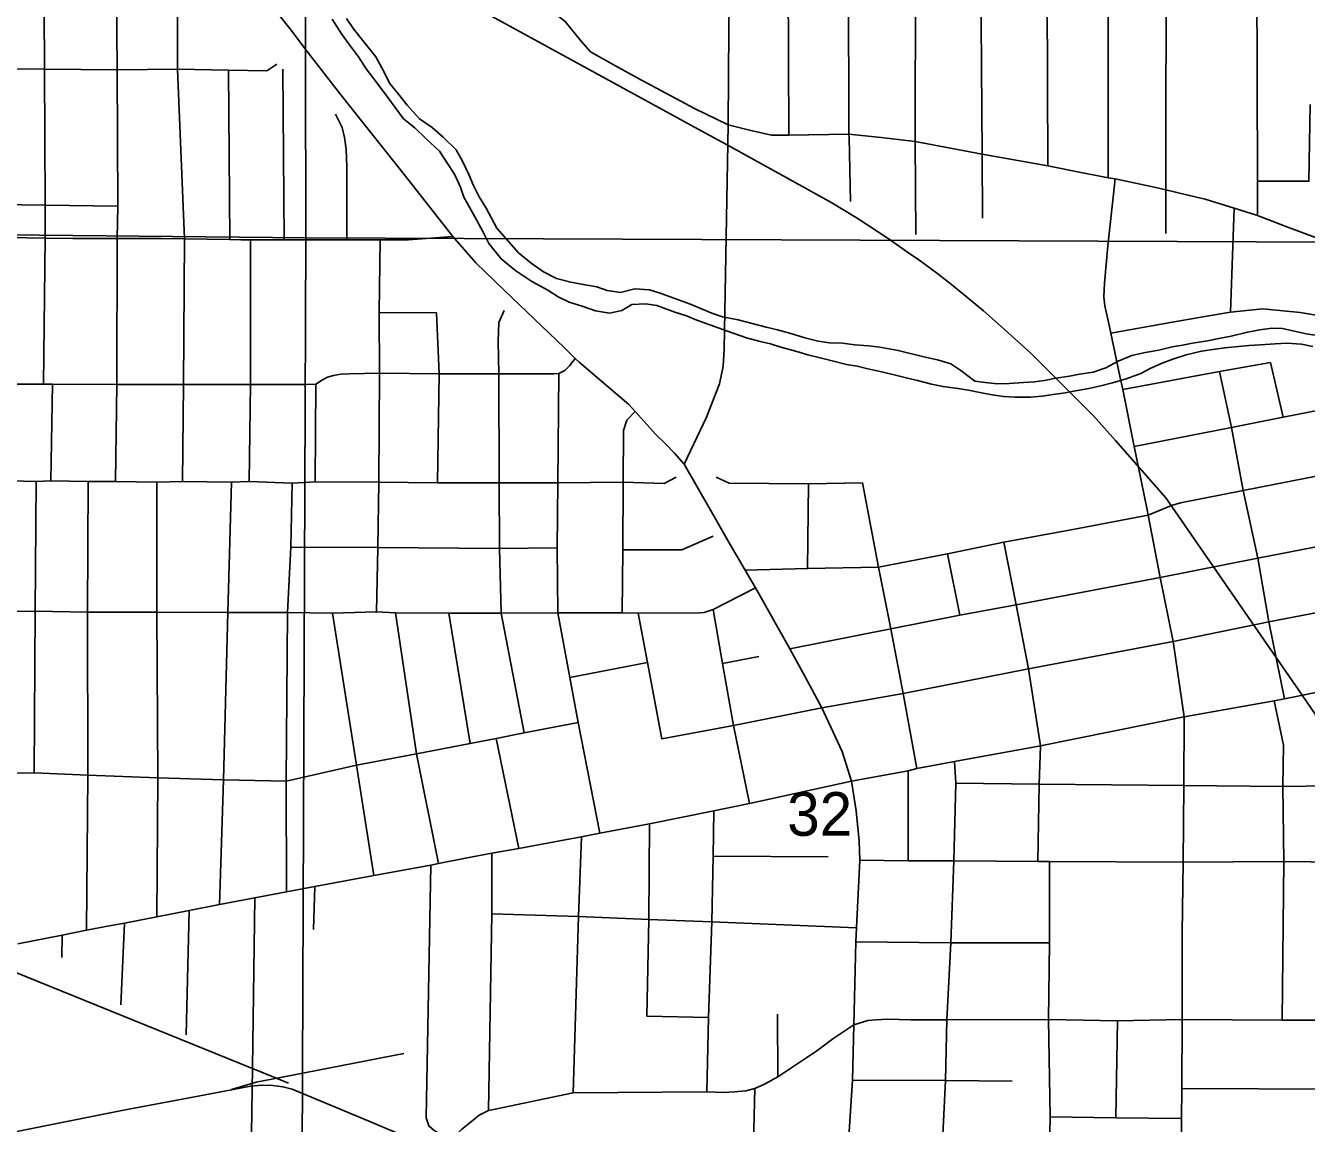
# Model space of a CAD drawing. Extents: x 0 to 34, y 0 to 22.
# Drawn here: x 3.784 to 5.012, y 17.64 to 18.692 of the extents above; entities that cross this region are included whole.
import ezdxf

# ---------------------------------------------------------------- set-up
doc = ezdxf.new("R2010")
doc.units = 0
for name, color, linetype in [('GM_X_City_Street', 7, 'Continuous'), ('GM_X_County_Road', 7, 'Continuous'), ('GM_X_Minor_River', 7, 'Continuous'), ('GM_X_Rail_Line', 7, 'Continuous'), ('GM_X_Section', 7, 'Continuous'), ('GM_X_Section_Text', 7, 'Continuous')]:
    doc.layers.add(name, color=color, linetype=linetype)

msp = doc.modelspace()

# ---------------------------------------------------------------- linework, layer by layer
at = {"layer": 'GM_X_City_Street'}
for p, q in [((4.7639, 18.5577), (4.7631, 18.738)), ((4.8218, 18.5464), (4.8217, 18.7386)), ((3.98, 18.4872), (3.9787, 18.6496)), ((4.032, 18.487), (4.0306, 18.6504)), ((4.5749, 18.5237), (4.5734, 18.5851)), ((4.9389, 18.4177), (4.9425, 18.5171)), ((4.123, 18.4171), (4.1778, 18.4168)), ((4.9895, 18.3168), (4.9774, 18.3694)), ((3.8082, 18.2558), (3.8099, 18.3485)), ((4.0618, 18.2551), (4.0624, 18.3484)), ((4.5336, 18.1718), (4.5344, 18.2531)), ((4.6795, 18.127), (4.6677, 18.1859)), ((4.2102, 18.0043), (4.1898, 18.129)), ((4.4868, 18.0874), (4.4521, 18.0808)), ((4.3803, 18.0817), (4.3058, 18.0675)), ((4.2568, 17.9035), (4.235, 18.0088)), ((4.63, 17.8916), (4.63, 17.978)), ((4.4431, 17.8962), (4.5534, 17.8954)), ((4.0601, 17.8258), (4.0613, 17.8672)), ((3.9381, 17.725), (3.9408, 17.8441)), ((3.8755, 17.7537), (3.8788, 17.8321)), ((3.8188, 17.7991), (3.8191, 17.8204)), ((4.3796, 17.7427), (4.4387, 17.7414)), ((4.5052, 17.6847), (4.5048, 17.7447)), ((4.8292, 17.6455), (4.8306, 17.7384)), ((4.8925, 17.6736), (5.0807, 17.6725))]:
    msp.add_line(p, q, dxfattribs=at)
for points in [[(4.5157, 18.5873), (4.5151, 18.7357), (4.5148, 18.8383)], [(3.8013, 18.3485), (3.8028, 18.4885), (3.8027, 18.5202), (3.8022, 18.6503), (3.8015, 18.7653), (3.8005, 18.8017), (3.8009, 18.8075), (3.8032, 18.8129), (3.8059, 18.8174), (3.8104, 18.8201), (3.8174, 18.8217), (3.8338, 18.8167)], [(3.8704, 18.2554), (3.8715, 18.3481), (3.8719, 18.4882), (3.8724, 18.5193), (3.8719, 18.6498), (3.8709, 18.7646), (3.8712, 18.8003), (3.8696, 18.8038), (3.8661, 18.8059), (3.8518, 18.8109), (3.8338, 18.8167)], [(3.9344, 18.2554), (3.9354, 18.3481), (3.9363, 18.4878), (3.9297, 18.6503), (3.9294, 18.7641), (3.9291, 18.7948)], [(4.5734, 18.5851), (4.5733, 18.5881), (4.5728, 18.7371)], [(4.6375, 18.4919), (4.6368, 18.581), (4.6371, 18.7379)], [(4.7013, 18.5077), (4.7011, 18.5691), (4.6996, 18.738)], [(4.8769, 18.4929), (4.8772, 18.5348), (4.8772, 18.5726), (4.8774, 18.7392)], [(4.964, 18.5105), (4.9649, 18.5114), (4.9648, 18.543), (4.9644, 18.7399)], [(4.2923, 18.7032), (4.3013, 18.6962), (4.3163, 18.6777), (4.3255, 18.6672), (4.3496, 18.6537), (4.371, 18.6419), (4.4251, 18.6126), (4.4575, 18.5971), (4.4793, 18.5918), (4.4991, 18.5873), (4.5157, 18.5873), (4.5733, 18.5881), (4.6043, 18.585), (4.6368, 18.581), (4.7011, 18.5691), (4.7639, 18.5577), (4.7972, 18.551), (4.809, 18.5488)], [(3.5997, 18.6513), (3.6641, 18.6509), (3.7331, 18.6511), (3.8022, 18.6503), (3.8719, 18.6498), (3.9297, 18.6503), (3.9787, 18.6496), (4.0152, 18.649), (4.0249, 18.6552)], [(4.9648, 18.543), (5.0142, 18.543), (5.0155, 18.6165)], [(4.092, 18.487), (4.092, 18.5568), (4.0915, 18.5738), (4.0897, 18.585), (4.0875, 18.5944), (4.0812, 18.6074)], [(4.809, 18.5488), (4.8218, 18.5464), (4.8284, 18.5452), (4.8674, 18.5369)], [(4.8227, 18.4051), (4.8185, 18.4235), (4.8175, 18.4324), (4.8181, 18.4453), (4.8216, 18.4812), (4.8284, 18.5452)], [(4.8674, 18.5369), (4.8772, 18.5348), (4.8969, 18.53)], [(4.8969, 18.53), (4.9146, 18.5257), (4.9425, 18.5171), (4.964, 18.5105), (4.965, 18.5102)], [(3.665, 18.5214), (3.734, 18.5211), (3.8027, 18.5202), (3.8724, 18.5193)], [(4.965, 18.5102), (4.9931, 18.4995), (5.023, 18.4882), (5.0685, 18.4711)], [(3.9984, 18.2554), (3.9998, 18.3481), (3.9996, 18.487)], [(4.1203, 18.1302), (4.1216, 18.1921), (4.1228, 18.2546), (4.1233, 18.359), (4.123, 18.4171), (4.1241, 18.487)], [(4.1789, 18.2541), (4.1804, 18.3586), (4.1778, 18.4168)], [(4.2621, 18.0145), (4.2399, 18.129), (4.2384, 18.1912), (4.2379, 18.2541), (4.2376, 18.3586), (4.2372, 18.3895), (4.2376, 18.4078), (4.2427, 18.4193)], [(4.8244, 18.3974), (4.8814, 18.4077), (4.9145, 18.4134), (4.9389, 18.4177), (4.97, 18.4209), (4.9764, 18.4202), (5.0058, 18.4172), (5.0685, 18.4066), (5.1056, 18.4003), (5.1258, 18.3975), (5.1402, 18.3945), (5.1892, 18.3828), (5.2629, 18.3574), (5.3225, 18.3403), (5.3816, 18.321), (5.4194, 18.3087), (5.4397, 18.3021), (5.455, 18.2985), (5.5002, 18.2901)], [(4.833, 18.3562), (4.8244, 18.3974), (4.8227, 18.4051)], [(3.6633, 18.3494), (3.6653, 18.3494), (3.7322, 18.3485), (3.8013, 18.3485), (3.8099, 18.3485), (3.8715, 18.3481), (3.9354, 18.3481), (3.9998, 18.3481), (4.0526, 18.3482), (4.0624, 18.3484), (4.0686, 18.3526), (4.0735, 18.3553), (4.0792, 18.3568), (4.0861, 18.358), (4.0942, 18.3585), (4.1233, 18.359), (4.1804, 18.3586), (4.2376, 18.3586), (4.2855, 18.3583), (4.2903, 18.3583), (4.2953, 18.3589), (4.3009, 18.3615), (4.3054, 18.366), (4.311, 18.3732)], [(4.8357, 18.3435), (4.9286, 18.3606), (4.9774, 18.3694)], [(4.3345, 17.9182), (4.3139, 18.0242), (4.3058, 18.0675), (4.2942, 18.1294), (4.2937, 18.1917), (4.2943, 18.254), (4.2953, 18.3589)], [(4.8591, 18.228), (4.8506, 18.2704), (4.8466, 18.2889), (4.8357, 18.3435), (4.833, 18.3562)], [(4.9908, 18.0471), (4.9759, 18.1208), (4.9653, 18.1819), (4.9513, 18.2465), (4.9401, 18.3071), (4.9286, 18.3606)], [(4.8466, 18.2889), (4.9401, 18.3071), (4.9895, 18.3168), (5.0666, 18.3319), (5.1349, 18.3451), (5.1807, 18.33), (5.2547, 18.3072), (5.3459, 18.2743)], [(4.3558, 18.1293), (4.3567, 18.1899), (4.357, 18.2545), (4.3571, 18.3043), (4.3603, 18.3142), (4.3683, 18.3224)], [(4.4738, 18.1703), (4.5336, 18.1718), (4.6016, 18.173), (4.6677, 18.1859), (4.7217, 18.1972), (4.7878, 18.2093), (4.8601, 18.223), (4.8824, 18.2321), (4.891, 18.2348), (4.9513, 18.2465), (5.0767, 18.2711)], [(3.7333, 18.2568), (3.7941, 18.2554), (3.8082, 18.2558), (3.8441, 18.2554), (3.8704, 18.2554), (3.9099, 18.2545), (3.9344, 18.2554), (3.9816, 18.2545), (3.9984, 18.2554), (4.0397, 18.2536), (4.0618, 18.2551), (4.1228, 18.2546), (4.1789, 18.2541), (4.2379, 18.2541), (4.2943, 18.254), (4.357, 18.2545), (4.3961, 18.2535), (4.4076, 18.2595)], [(4.4459, 18.2595), (4.4586, 18.2536), (4.5344, 18.2531), (4.5862, 18.2539)], [(5.427, 18.2509), (5.3978, 18.2584), (5.3849, 18.2618), (5.3799, 18.262), (5.3739, 18.2608), (5.3617, 18.2586), (5.3452, 18.2552), (5.2442, 18.2367), (5.1724, 18.2226), (5.0904, 18.2061), (4.9653, 18.1819), (4.8716, 18.1633), (4.7336, 18.1371), (4.6795, 18.127), (4.6136, 18.1142), (4.5165, 18.0948)], [(3.7923, 17.976), (3.7933, 18.1311), (3.7941, 18.2554)], [(3.8426, 17.8251), (3.8439, 17.9739), (3.8435, 18.13), (3.8441, 18.2554)], [(3.9098, 17.8381), (3.9108, 17.9713), (3.9099, 18.13), (3.9099, 18.2545)], [(3.9698, 17.8498), (3.9739, 17.9692), (3.9778, 18.1296), (3.9816, 18.2545)], [(4.0341, 17.862), (4.0339, 17.9679), (4.035, 18.1298), (4.0382, 18.1922), (4.0397, 18.2536)], [(4.6383, 17.9801), (4.6253, 18.0522), (4.6136, 18.1142), (4.6016, 18.173), (4.5862, 18.2539)], [(4.8946, 18.0297), (4.884, 18.1018), (4.8716, 18.1633), (4.8601, 18.223), (4.8591, 18.228)], [(4.3938, 18.0085), (4.4627, 18.0213), (4.5474, 18.0382), (4.6253, 18.0522), (4.7455, 18.0758), (4.884, 18.1018), (4.9759, 18.1208), (5.1022, 18.145), (5.2069, 18.1661), (5.2356, 18.1707), (5.3407, 18.1919), (5.3573, 18.1952), (5.4357, 18.2104)], [(4.3567, 18.1899), (4.4132, 18.1899), (4.443, 18.203)], [(4.7568, 18.002), (4.7455, 18.0758), (4.7336, 18.1371), (4.7217, 18.1972)], [(4.0382, 18.1922), (4.1216, 18.1921), (4.2384, 18.1912), (4.2937, 18.1917)], [(4.8946, 18.0297), (4.9808, 18.045), (4.9908, 18.0471), (5.1161, 18.0723), (5.1925, 18.0873), (5.2219, 18.0934), (5.2784, 18.1052), (5.3074, 18.1106), (5.3545, 18.1194), (5.3643, 18.1212), (5.3826, 18.1248), (5.426, 18.1334), (5.4498, 18.1382), (5.4902, 18.1462), (5.528, 18.1531), (5.5468, 18.1593), (5.566, 18.1633)], [(3.7308, 18.1306), (3.7933, 18.1311), (3.8435, 18.13), (3.9099, 18.13), (3.9778, 18.1296), (4.035, 18.1298), (4.0784, 18.129), (4.1203, 18.1302), (4.1386, 18.1294), (4.1898, 18.129), (4.2399, 18.129), (4.2942, 18.1294), (4.3558, 18.1293), (4.3714, 18.129), (4.4301, 18.1293), (4.4344, 18.1298), (4.443, 18.1327), (4.4836, 18.1535)], [(4.4781, 17.9466), (4.4627, 18.0213), (4.4521, 18.0808), (4.443, 18.1327)], [(4.118, 17.8777), (4.1012, 17.9833), (4.0784, 18.129)], [(4.18, 17.889), (4.1587, 17.9942), (4.1386, 18.1294)], [(4.3938, 18.0085), (4.3803, 18.0817), (4.3714, 18.129)], [(4.9886, 17.7389), (4.99, 17.8911), (4.9893, 17.9628), (4.9898, 18.0026), (4.9808, 18.045)], [(3.296, 17.9794), (3.3466, 17.9778), (3.4172, 17.9776), (3.5342, 17.9772), (3.5976, 17.9768), (3.6612, 17.9767), (3.7277, 17.9767), (3.7808, 17.9756), (3.7923, 17.976), (3.8439, 17.9739), (3.9108, 17.9713), (3.9739, 17.9692), (4.0339, 17.9679), (4.1012, 17.9833), (4.1587, 17.9942), (4.2102, 18.0043), (4.235, 18.0088), (4.2621, 18.0145), (4.3139, 18.0242)], [(4.5759, 17.9679), (4.63, 17.978), (4.6383, 17.9801), (4.6746, 17.9868), (4.7568, 18.002), (4.8946, 18.0297)], [(4.8946, 17.4586), (4.8927, 17.5074), (4.8926, 17.5199), (4.8925, 17.5655), (4.8921, 17.6044), (4.8921, 17.6448), (4.8925, 17.6736), (4.8928, 17.7397), (4.8928, 17.8223), (4.8938, 17.8905), (4.8943, 17.9638), (4.8946, 18.0297)], [(4.7545, 17.8912), (4.7555, 17.9653), (4.7568, 18.002)], [(4.6738, 17.8916), (4.6756, 17.9661), (4.6746, 17.9868)], [(3.7765, 17.812), (3.8191, 17.8204), (3.8426, 17.8251), (3.8626, 17.829), (3.8788, 17.8321), (3.9098, 17.8381), (3.9408, 17.8441), (3.9698, 17.8498), (4.0039, 17.8562), (4.0341, 17.862), (4.0613, 17.8672), (4.0752, 17.8698), (4.118, 17.8777), (4.1726, 17.8876), (4.18, 17.889), (4.2057, 17.8943), (4.231, 17.8991), (4.2568, 17.9035), (4.3064, 17.9129), (4.3168, 17.9148), (4.3345, 17.9182), (4.382, 17.9273), (4.4439, 17.9397), (4.4781, 17.9466), (4.5759, 17.9679)], [(4.6756, 17.9661), (4.7555, 17.9653), (4.8943, 17.9638), (4.9893, 17.9628), (5.0335, 17.9635), (5.0519, 17.9614), (5.0781, 17.9578), (5.12, 17.9512), (5.2013, 17.9387)], [(4.4372, 17.6704), (4.4387, 17.7414), (4.442, 17.8333), (4.4431, 17.8962), (4.4439, 17.9397)], [(4.3796, 17.7427), (4.3814, 17.8355), (4.382, 17.9273)], [(4.3091, 17.6692), (4.3141, 17.8383), (4.3168, 17.9148)], [(4.5836, 17.8922), (4.63, 17.8916), (4.6738, 17.8916), (4.7545, 17.8912), (4.7656, 17.8911), (4.8938, 17.8905), (4.99, 17.8911), (5.0672, 17.8902), (5.1126, 17.8907), (5.1933, 17.888), (5.2606, 17.8879), (5.2922, 17.8883), (5.3133, 17.8892), (5.3279, 17.8895), (5.3741, 17.8904), (5.3818, 17.8914), (5.456, 17.9009), (5.5128, 17.9074)], [(4.1942, 17.6262), (4.1801, 17.6307), (4.1758, 17.6333), (4.1707, 17.6376), (4.1681, 17.6453), (4.1726, 17.8876)], [(4.2278, 17.6524), (4.2309, 17.841), (4.231, 17.8991)], [(4.6669, 17.586), (4.6633, 17.5928), (4.6624, 17.5969), (4.6632, 17.6292), (4.666, 17.6811), (4.6672, 17.7392), (4.6711, 17.8132), (4.6738, 17.8916)], [(4.7641, 17.5672), (4.7662, 17.644), (4.7662, 17.6463), (4.7647, 17.7396), (4.7654, 17.8132), (4.7656, 17.8911)], [(3.9999, 17.5871), (4.0015, 17.6935), (4.0039, 17.8562)], [(4.2309, 17.841), (4.3141, 17.8383), (4.3814, 17.8355), (4.442, 17.8333), (4.5806, 17.8276)], [(4.58, 17.814), (4.6711, 17.8132), (4.7654, 17.8132)], [(4.2343, 17.6538), (4.3091, 17.6692), (4.4372, 17.6704), (4.4526, 17.6698), (4.4637, 17.6703), (4.4745, 17.6714), (4.4831, 17.6736), (4.4925, 17.6778), (4.5052, 17.6847), (4.5425, 17.7096), (4.5577, 17.7211), (4.5779, 17.7346)], [(4.5779, 17.7346), (4.5913, 17.7388), (4.5994, 17.7394), (4.6102, 17.7398), (4.6326, 17.7394), (4.6672, 17.7392), (4.7647, 17.7396), (4.8306, 17.7384), (4.8928, 17.7397), (4.9886, 17.7389), (5.0457, 17.7389), (5.0902, 17.739), (5.1727, 17.7377)], [(4.5766, 17.6815), (4.666, 17.6811), (4.7296, 17.6806)], [(4.4878, 17.6169), (4.4819, 17.621), (4.4831, 17.6736)], [(3.7696, 17.5067), (3.8107, 17.5145), (3.9018, 17.5292), (3.9512, 17.5379), (4.006, 17.5472), (4.0098, 17.5479), (4.0719, 17.557), (4.1372, 17.5684), (4.1439, 17.5703), (4.1504, 17.5728), (4.1551, 17.575), (4.1633, 17.581), (4.1694, 17.5862), (4.1762, 17.5931), (4.1837, 17.6055), (4.1879, 17.6125), (4.1911, 17.6194), (4.1942, 17.6262), (4.2019, 17.6342), (4.2098, 17.6407), (4.2187, 17.6479), (4.2278, 17.6524), (4.2343, 17.6538)], [(4.7662, 17.6463), (4.8292, 17.6455), (4.8921, 17.6448)]]:
    msp.add_lwpolyline(points, dxfattribs=at)
at = {"layer": 'GM_X_County_Road'}
for points in [[(4.4575, 18.5971), (4.4585, 18.7358), (4.4579, 18.8372), (4.4596, 18.9102), (4.4579, 18.9712), (4.4578, 18.9772)], [(3.7317, 18.8659), (3.8144, 18.8416), (3.8859, 18.8163), (3.9095, 18.8064), (3.9291, 18.7948), (3.9423, 18.7865), (3.9632, 18.7706), (3.9784, 18.7571), (3.995, 18.741), (4.0106, 18.7234), (4.0385, 18.6879), (4.0519, 18.6704), (4.0861, 18.6257), (4.1483, 18.5479), (4.1937, 18.4902), (4.2156, 18.4647), (4.243, 18.4383), (4.3002, 18.3836)], [(4.4155, 18.272), (4.4369, 18.3169), (4.4493, 18.349), (4.4527, 18.3657), (4.4536, 18.3821), (4.4575, 18.5971)], [(3.6642, 18.49), (3.7342, 18.4893), (3.75, 18.4893), (3.8028, 18.4885), (3.8293, 18.4882), (3.8719, 18.4882), (3.9145, 18.4882), (3.9363, 18.4878), (3.98, 18.4872), (3.9903, 18.487), (3.9996, 18.487), (4.032, 18.487), (4.092, 18.487), (4.1241, 18.487), (4.1512, 18.487), (4.1937, 18.4902)], [(4.3002, 18.3836), (4.311, 18.3732), (4.3148, 18.3696), (4.3622, 18.3292), (4.3683, 18.3224), (4.3745, 18.3155), (4.3875, 18.301), (4.3971, 18.2918), (4.4061, 18.2824), (4.4155, 18.272), (4.4391, 18.2308), (4.4585, 18.1965), (4.4738, 18.1703), (4.4836, 18.1535), (4.4877, 18.1465), (4.5165, 18.0948), (4.5314, 18.068), (4.5474, 18.0382), (4.5669, 17.9964), (4.5759, 17.9679)], [(4.5759, 17.9679), (4.5801, 17.9395), (4.5831, 17.9107), (4.5836, 17.8922), (4.5806, 17.8276), (4.58, 17.814), (4.5786, 17.7603), (4.5779, 17.7346), (4.5766, 17.6815), (4.5729, 17.6225), (4.5718, 17.6034), (4.5706, 17.5721), (4.5704, 17.5667), (4.5702, 17.5616), (4.5689, 17.5355)]]:
    msp.add_lwpolyline(points, dxfattribs=at)
at = {"layer": 'GM_X_Minor_River'}
for points in [[(4.078, 18.6985), (4.0868, 18.6843), (4.0946, 18.6739), (4.1031, 18.6623), (4.1105, 18.6507), (4.1179, 18.6411), (4.1286, 18.6268), (4.1382, 18.6137), (4.1464, 18.6029), (4.1572, 18.5943), (4.1677, 18.5839), (4.1807, 18.5718), (4.1885, 18.5599), (4.1951, 18.5499), (4.2009, 18.5372), (4.2042, 18.5277), (4.21, 18.5177), (4.2163, 18.5061), (4.2225, 18.495), (4.228, 18.4835), (4.2398, 18.4688), (4.254, 18.4571), (4.2694, 18.4469), (4.2848, 18.4386), (4.2946, 18.4324), (4.3051, 18.4272), (4.3176, 18.4232), (4.3304, 18.4187), (4.3437, 18.4166), (4.3555, 18.419), (4.3651, 18.4249), (4.3784, 18.4257), (4.389, 18.424), (4.4064, 18.4176), (4.4177, 18.4139), (4.4275, 18.4099), (4.4524, 18.401), (4.4622, 18.3974), (4.475, 18.393), (4.4882, 18.3893), (4.4981, 18.3872), (4.5079, 18.384), (4.5234, 18.3799), (4.5339, 18.3766), (4.5457, 18.3737), (4.5559, 18.3712), (4.571, 18.3675), (4.5812, 18.3658), (4.5914, 18.3633), (4.6032, 18.3608), (4.6168, 18.3574), (4.6281, 18.3546), (4.6391, 18.3521), (4.6523, 18.3487), (4.6636, 18.3462), (4.6777, 18.3444), (4.6879, 18.3427), (4.6989, 18.3406), (4.7087, 18.3385), (4.7216, 18.3367), (4.7322, 18.3361), (4.7474, 18.3362), (4.7584, 18.3371), (4.7691, 18.3388), (4.7805, 18.3404), (4.7904, 18.3421), (4.8034, 18.3445), (4.8149, 18.347), (4.8259, 18.3498), (4.8389, 18.3537), (4.8531, 18.3587), (4.8627, 18.3638), (4.8734, 18.3686), (4.8837, 18.3725), (4.8964, 18.3768), (4.9112, 18.3803), (4.9242, 18.382), (4.9337, 18.3833), (4.9466, 18.3846), (4.9565, 18.3855), (4.9676, 18.3864), (4.982, 18.3873), (4.9931, 18.3878), (5.0071, 18.3868), (5.0181, 18.3846)], [(5.0266, 18.3947), (5.0115, 18.3969), (4.9888, 18.4019), (4.9785, 18.4022), (4.9671, 18.4005), (4.9553, 18.3984), (4.9396, 18.3946), (4.9278, 18.3922), (4.9171, 18.3901), (4.9026, 18.3877), (4.8931, 18.386), (4.8832, 18.3843), (4.8702, 18.3812), (4.8573, 18.3788), (4.8443, 18.376), (4.8313, 18.3706), (4.8194, 18.3643), (4.8075, 18.36), (4.7942, 18.358), (4.7846, 18.3563), (4.7717, 18.3543), (4.7606, 18.3522), (4.7511, 18.3509), (4.7405, 18.35), (4.7268, 18.3491), (4.7154, 18.349), (4.704, 18.35), (4.6941, 18.3513), (4.6807, 18.3615), (4.6709, 18.3681), (4.6581, 18.3718), (4.6452, 18.3747), (4.6206, 18.3809), (4.6029, 18.3839), (4.5919, 18.3853), (4.579, 18.3863), (4.5672, 18.3877), (4.5547, 18.3883), (4.5437, 18.3897), (4.5309, 18.393), (4.5176, 18.3971), (4.5048, 18.4007), (4.4938, 18.4032), (4.4806, 18.4066), (4.467, 18.4102), (4.4522, 18.4132), (4.442, 18.4165), (4.4319, 18.4208), (4.4206, 18.4256), (4.3923, 18.4357), (4.3821, 18.4389), (4.3681, 18.44), (4.3543, 18.4365), (4.3414, 18.4383), (4.3316, 18.4419), (4.3203, 18.4436), (4.3066, 18.4462), (4.293, 18.4499), (4.2806, 18.4562), (4.2686, 18.4644), (4.2567, 18.4745), (4.2474, 18.485), (4.2359, 18.4981), (4.2256, 18.5173), (4.219, 18.5281), (4.2131, 18.5396), (4.2088, 18.5496), (4.2029, 18.5623), (4.1967, 18.573), (4.1844, 18.5854), (4.1739, 18.5944), (4.1616, 18.603), (4.1497, 18.6158), (4.1415, 18.6266), (4.133, 18.637), (4.1275, 18.6481), (4.1198, 18.6623), (4.1083, 18.6766), (4.0983, 18.689), (4.0917, 18.699)]]:
    msp.add_lwpolyline(points, dxfattribs=at)
at = {"layer": 'GM_X_Rail_Line'}
msp.add_line((4.0235, 17.6837), (4.0361, 17.6786), dxfattribs=at)
for points in [[(4.4322, 18.5911), (4.354, 18.6337), (4.039, 18.8064), (3.9364, 18.8625), (3.5545, 19.0718), (3.4463, 19.1312), (3.329, 19.1955), (3.2341, 19.2473), (3.176, 19.2792), (3.1246, 19.3074), (3.0275, 19.3605), (2.901, 19.4294), (2.7445, 19.5149), (2.6572, 19.5627), (2.5791, 19.6051), (2.4361, 19.6837), (2.3902, 19.7084), (2.2433, 19.7883)], [(2.3898, 19.7064), (2.7075, 19.2523), (2.7388, 19.2043), (2.765, 19.1563), (2.8452, 18.9696), (3.1958, 18.2158), (3.251, 18.1014), (3.28, 18.041), (3.3284, 17.9975), (3.3695, 17.9588), (3.4444, 17.9225), (3.727, 17.8039), (4.0235, 17.6837)], [(5.0468, 17.9936), (5.0041, 18.0555), (4.8769, 18.2396), (4.8289, 18.2946), (4.8078, 18.3182), (4.748, 18.3779), (4.7193, 18.4039), (4.7022, 18.4189), (4.6857, 18.4325), (4.6717, 18.4441), (4.6584, 18.4543), (4.6403, 18.4676), (4.6285, 18.4758), (4.6119, 18.4876), (4.5811, 18.5077), (4.557, 18.5222), (4.5311, 18.5368), (4.4587, 18.5767), (4.4322, 18.5911)], [(3.9814, 17.6724), (4.005, 17.6795), (4.0284, 17.684), (4.1466, 17.7071)], [(5.061, 17.3541), (5.0018, 17.3488), (4.9087, 17.3403), (4.8969, 17.3395), (4.8784, 17.3394), (4.8627, 17.3402), (4.8503, 17.3415), (4.838, 17.3435), (4.8242, 17.3461), (4.8106, 17.3496), (4.7966, 17.3541), (4.7364, 17.3793), (4.6346, 17.4219), (4.1123, 17.6425), (4.0396, 17.6729), (4.0308, 17.6752), (4.0212, 17.6764), (4.0106, 17.6766), (3.9996, 17.6757), (3.9815, 17.6722), (3.9444, 17.6652), (3.8779, 17.6527), (3.7401, 17.6252)]]:
    msp.add_lwpolyline(points, dxfattribs=at)
at = {"layer": 'GM_X_Section'}
for points in [[(3.0286, 19.513), (4.0509, 19.5018), (4.0528, 18.4887), (3.031, 18.499)], [(5.0371, 19.5016), (5.0397, 18.4846), (4.0528, 18.4887), (4.0509, 19.5018)], [(3.031, 18.499), (4.0528, 18.4887), (4.0485, 17.4495), (3.1709, 17.4714), (3.0196, 17.4831)], [(4.0528, 18.4887), (5.0397, 18.4846), (5.0461, 17.3925), (4.0485, 17.4495)]]:
    msp.add_lwpolyline(points, close=True, dxfattribs=at)

# ---------------------------------------------------------------- texts
at = {"layer": 'GM_X_Section_Text'}
msp.add_text('32', height=0.04186, rotation=0, dxfattribs=at).set_placement((4.5141, 17.9157))

doc.saveas('drawing.dxf')
